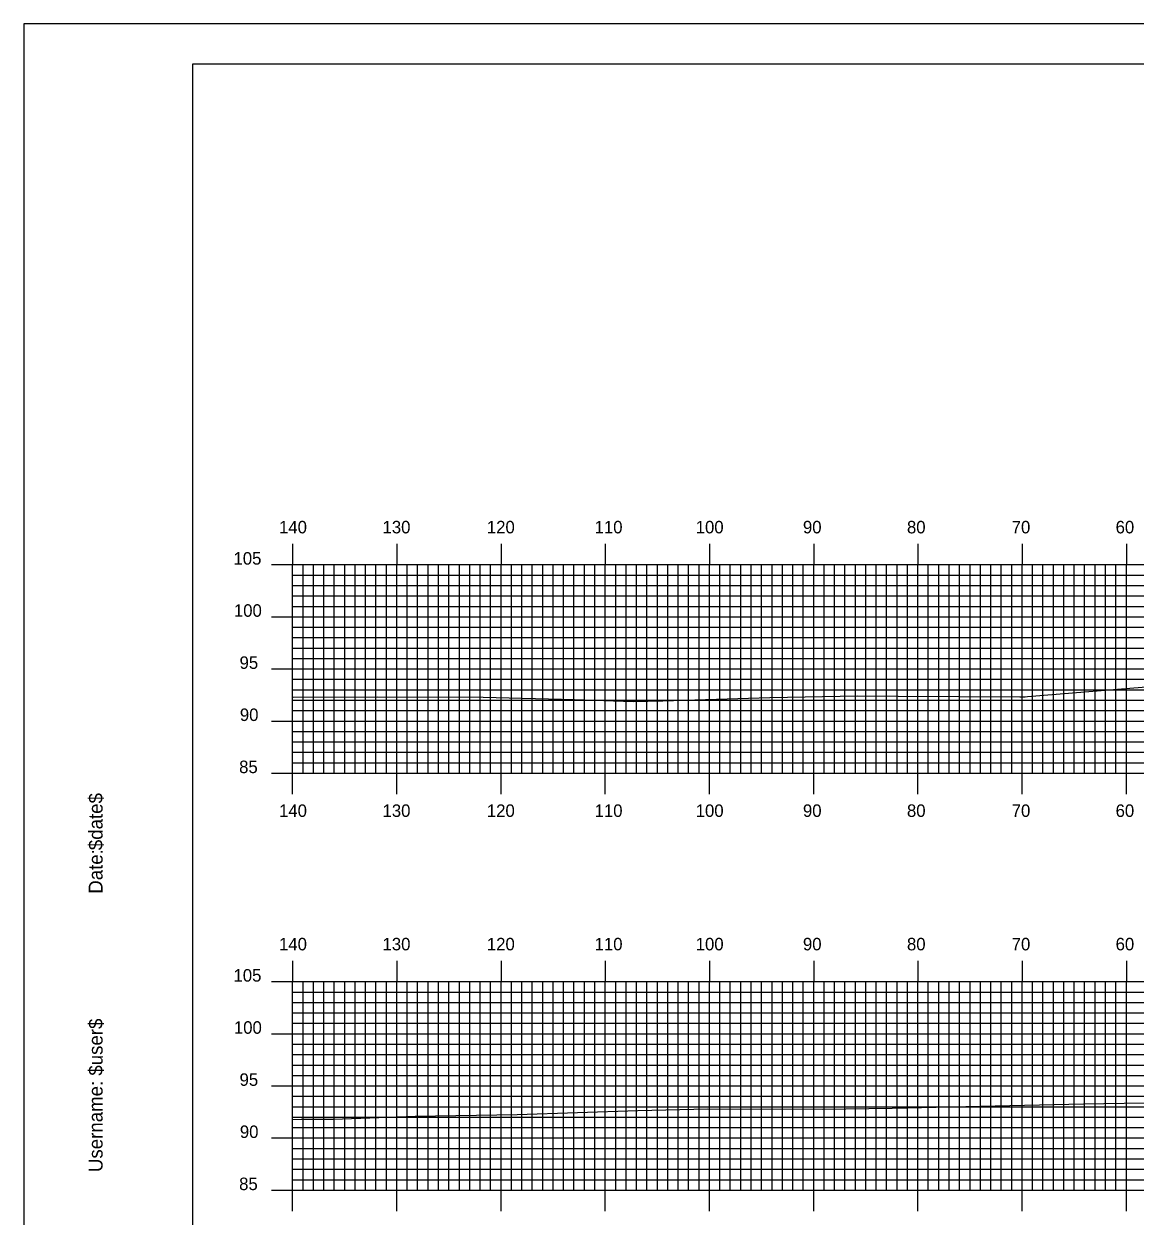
# Model space of a CAD drawing. Extents: x 1763759 to 1764102, y 442591 to 442811.
# Drawn here: x 1763758.5 to 1763865.2, y 442696.2 to 442810.5 of the extents above; entities that cross this region are included whole.
import ezdxf

# ---------------------------------------------------------------- set-up
doc = ezdxf.new("R2010")
doc.units = 0
for name, color, linetype in [('BORDER', 7, 'Continuous'), ('H_V ANNOTATION', 7, 'Continuous'), ('MAJOR', 7, 'Continuous'), ('MINOR', 7, 'Continuous'), ('PLOT BOUNDARY', 7, 'Continuous'), ('S_Roadway_Centerline', 7, 'Continuous')]:
    doc.layers.add(name, color=color, linetype=linetype)

msp = doc.modelspace()

# ---------------------------------------------------------------- linework, layer by layer
at = {"layer": 'BORDER'}
msp.add_lwpolyline([(1763774.72, 442596.67), (1764094.72, 442596.67), (1764094.72, 442806.67), (1763774.72, 442806.67)], close=True, dxfattribs=at)
at = {"layer": 'MAJOR'}
for p, q in [((1763784.32, 442760.67), (1763784.32, 442758.67)), ((1763794.32, 442760.67), (1763794.32, 442758.67)), ((1763804.32, 442760.67), (1763804.32, 442758.67)), ((1763814.32, 442760.67), (1763814.32, 442758.67)), ((1763824.32, 442760.67), (1763824.32, 442758.67)), ((1763834.32, 442760.67), (1763834.32, 442758.67)), ((1763844.32, 442760.67), (1763844.32, 442758.67)), ((1763854.32, 442760.67), (1763854.32, 442758.67)), ((1763864.32, 442760.67), (1763864.32, 442758.67)), ((1763782.31, 442758.67), (1763784.32, 442758.67)), ((1763784.32, 442758.67), (1764064.32, 442758.67)), ((1763784.32, 442738.67), (1763784.32, 442758.67)), ((1763784.32, 442738.67), (1763784.32, 442758.67)), ((1763784.32, 442758.67), (1764064.32, 442758.67)), ((1763794.32, 442738.67), (1763794.32, 442758.67)), ((1763804.32, 442738.67), (1763804.32, 442758.67)), ((1763814.32, 442738.67), (1763814.32, 442758.67)), ((1763824.32, 442738.67), (1763824.32, 442758.67)), ((1763834.32, 442738.67), (1763834.32, 442758.67)), ((1763844.32, 442738.67), (1763844.32, 442758.67)), ((1763854.32, 442738.67), (1763854.32, 442758.67)), ((1763864.32, 442738.67), (1763864.32, 442758.67)), ((1763782.31, 442753.67), (1763784.32, 442753.67)), ((1763784.32, 442753.67), (1764064.32, 442753.67)), ((1763782.31, 442748.67), (1763784.32, 442748.67)), ((1763784.32, 442748.67), (1764064.32, 442748.67)), ((1763782.31, 442743.67), (1763784.32, 442743.67)), ((1763784.32, 442743.67), (1764064.32, 442743.67)), ((1763782.31, 442738.67), (1763784.32, 442738.67)), ((1763784.32, 442738.67), (1764064.32, 442738.67)), ((1763784.32, 442738.67), (1764064.32, 442738.67)), ((1763784.32, 442736.66), (1763784.32, 442738.67)), ((1763794.32, 442736.66), (1763794.32, 442738.67)), ((1763804.32, 442736.66), (1763804.32, 442738.67)), ((1763814.32, 442736.66), (1763814.32, 442738.67)), ((1763824.32, 442736.66), (1763824.32, 442738.67)), ((1763834.32, 442736.66), (1763834.32, 442738.67)), ((1763844.32, 442736.66), (1763844.32, 442738.67)), ((1763854.32, 442736.66), (1763854.32, 442738.67)), ((1763864.32, 442736.66), (1763864.32, 442738.67)), ((1763784.32, 442720.67), (1763784.32, 442718.67)), ((1763794.32, 442720.67), (1763794.32, 442718.67)), ((1763804.32, 442720.67), (1763804.32, 442718.67)), ((1763814.32, 442720.67), (1763814.32, 442718.67)), ((1763824.32, 442720.67), (1763824.32, 442718.67)), ((1763834.32, 442720.67), (1763834.32, 442718.67)), ((1763844.32, 442720.67), (1763844.32, 442718.67)), ((1763854.32, 442720.67), (1763854.32, 442718.67)), ((1763864.32, 442720.67), (1763864.32, 442718.67)), ((1763782.31, 442718.67), (1763784.32, 442718.67)), ((1763784.32, 442718.67), (1764064.32, 442718.67)), ((1763784.32, 442698.67), (1763784.32, 442718.67)), ((1763784.32, 442698.67), (1763784.32, 442718.67)), ((1763784.32, 442718.67), (1764064.32, 442718.67)), ((1763794.32, 442698.67), (1763794.32, 442718.67)), ((1763804.32, 442698.67), (1763804.32, 442718.67)), ((1763814.32, 442698.67), (1763814.32, 442718.67)), ((1763824.32, 442698.67), (1763824.32, 442718.67)), ((1763834.32, 442698.67), (1763834.32, 442718.67)), ((1763844.32, 442698.67), (1763844.32, 442718.67)), ((1763854.32, 442698.67), (1763854.32, 442718.67)), ((1763864.32, 442698.67), (1763864.32, 442718.67)), ((1763782.31, 442713.67), (1763784.32, 442713.67)), ((1763784.32, 442713.67), (1764064.32, 442713.67)), ((1763782.31, 442708.67), (1763784.32, 442708.67)), ((1763784.32, 442708.67), (1764064.32, 442708.67)), ((1763782.31, 442703.67), (1763784.32, 442703.67)), ((1763784.32, 442703.67), (1764064.32, 442703.67)), ((1763782.31, 442698.67), (1763784.32, 442698.67)), ((1763784.32, 442698.67), (1764064.32, 442698.67)), ((1763784.32, 442698.67), (1764064.32, 442698.67)), ((1763784.32, 442696.66), (1763784.32, 442698.67)), ((1763794.32, 442696.66), (1763794.32, 442698.67)), ((1763804.32, 442696.66), (1763804.32, 442698.67)), ((1763814.32, 442696.66), (1763814.32, 442698.67)), ((1763824.32, 442696.66), (1763824.32, 442698.67)), ((1763834.32, 442696.66), (1763834.32, 442698.67)), ((1763844.32, 442696.66), (1763844.32, 442698.67)), ((1763854.32, 442696.66), (1763854.32, 442698.67)), ((1763864.32, 442696.66), (1763864.32, 442698.67))]:
    msp.add_line(p, q, dxfattribs=at)
at = {"layer": 'MINOR'}
for p, q in [((1763785.32, 442738.67), (1763785.32, 442758.67)), ((1763786.32, 442738.67), (1763786.32, 442758.67)), ((1763787.32, 442738.67), (1763787.32, 442758.67)), ((1763788.32, 442738.67), (1763788.32, 442758.67)), ((1763789.32, 442738.67), (1763789.32, 442758.67)), ((1763790.32, 442738.67), (1763790.32, 442758.67)), ((1763791.32, 442738.67), (1763791.32, 442758.67)), ((1763792.32, 442738.67), (1763792.32, 442758.67)), ((1763793.32, 442738.67), (1763793.32, 442758.67)), ((1763795.32, 442738.67), (1763795.32, 442758.67)), ((1763796.32, 442738.67), (1763796.32, 442758.67)), ((1763797.32, 442738.67), (1763797.32, 442758.67)), ((1763798.32, 442738.67), (1763798.32, 442758.67)), ((1763799.32, 442738.67), (1763799.32, 442758.67)), ((1763800.32, 442738.67), (1763800.32, 442758.67)), ((1763801.32, 442738.67), (1763801.32, 442758.67)), ((1763802.32, 442738.67), (1763802.32, 442758.67)), ((1763803.32, 442738.67), (1763803.32, 442758.67)), ((1763805.32, 442738.67), (1763805.32, 442758.67)), ((1763806.32, 442738.67), (1763806.32, 442758.67)), ((1763807.32, 442738.67), (1763807.32, 442758.67)), ((1763808.32, 442738.67), (1763808.32, 442758.67)), ((1763809.32, 442738.67), (1763809.32, 442758.67)), ((1763810.32, 442738.67), (1763810.32, 442758.67)), ((1763811.32, 442738.67), (1763811.32, 442758.67)), ((1763812.32, 442738.67), (1763812.32, 442758.67)), ((1763813.32, 442738.67), (1763813.32, 442758.67)), ((1763815.32, 442738.67), (1763815.32, 442758.67)), ((1763816.32, 442738.67), (1763816.32, 442758.67)), ((1763817.32, 442738.67), (1763817.32, 442758.67)), ((1763818.32, 442738.67), (1763818.32, 442758.67)), ((1763819.32, 442738.67), (1763819.32, 442758.67)), ((1763820.32, 442738.67), (1763820.32, 442758.67)), ((1763821.32, 442738.67), (1763821.32, 442758.67)), ((1763822.32, 442738.67), (1763822.32, 442758.67)), ((1763823.32, 442738.67), (1763823.32, 442758.67)), ((1763825.32, 442738.67), (1763825.32, 442758.67)), ((1763826.32, 442738.67), (1763826.32, 442758.67)), ((1763827.32, 442738.67), (1763827.32, 442758.67)), ((1763828.32, 442738.67), (1763828.32, 442758.67)), ((1763829.32, 442738.67), (1763829.32, 442758.67)), ((1763830.32, 442738.67), (1763830.32, 442758.67)), ((1763831.32, 442738.67), (1763831.32, 442758.67)), ((1763832.32, 442738.67), (1763832.32, 442758.67)), ((1763833.32, 442738.67), (1763833.32, 442758.67)), ((1763835.32, 442738.67), (1763835.32, 442758.67)), ((1763836.32, 442738.67), (1763836.32, 442758.67)), ((1763837.32, 442738.67), (1763837.32, 442758.67)), ((1763838.32, 442738.67), (1763838.32, 442758.67)), ((1763839.32, 442738.67), (1763839.32, 442758.67)), ((1763840.32, 442738.67), (1763840.32, 442758.67)), ((1763841.32, 442738.67), (1763841.32, 442758.67)), ((1763842.32, 442738.67), (1763842.32, 442758.67)), ((1763843.32, 442738.67), (1763843.32, 442758.67)), ((1763845.32, 442738.67), (1763845.32, 442758.67)), ((1763846.32, 442738.67), (1763846.32, 442758.67)), ((1763847.32, 442738.67), (1763847.32, 442758.67)), ((1763848.32, 442738.67), (1763848.32, 442758.67)), ((1763849.32, 442738.67), (1763849.32, 442758.67)), ((1763850.32, 442738.67), (1763850.32, 442758.67)), ((1763851.32, 442738.67), (1763851.32, 442758.67)), ((1763852.32, 442738.67), (1763852.32, 442758.67)), ((1763853.32, 442738.67), (1763853.32, 442758.67)), ((1763855.32, 442738.67), (1763855.32, 442758.67)), ((1763856.32, 442738.67), (1763856.32, 442758.67)), ((1763857.32, 442738.67), (1763857.32, 442758.67)), ((1763858.32, 442738.67), (1763858.32, 442758.67)), ((1763859.32, 442738.67), (1763859.32, 442758.67)), ((1763860.32, 442738.67), (1763860.32, 442758.67)), ((1763861.32, 442738.67), (1763861.32, 442758.67)), ((1763862.32, 442738.67), (1763862.32, 442758.67)), ((1763863.32, 442738.67), (1763863.32, 442758.67)), ((1763784.32, 442757.67), (1764064.32, 442757.67)), ((1763784.32, 442757.67), (1763786.32, 442757.67)), ((1763784.32, 442756.67), (1764064.32, 442756.67)), ((1763784.32, 442756.67), (1763786.32, 442756.67)), ((1763784.32, 442755.67), (1764064.32, 442755.67)), ((1763784.32, 442755.67), (1763786.32, 442755.67)), ((1763784.32, 442754.67), (1764064.32, 442754.67)), ((1763784.32, 442754.67), (1763786.32, 442754.67)), ((1763784.32, 442752.67), (1764064.32, 442752.67)), ((1763784.32, 442752.67), (1763786.32, 442752.67)), ((1763784.32, 442751.67), (1764064.32, 442751.67)), ((1763784.32, 442751.67), (1763786.32, 442751.67)), ((1763784.32, 442750.67), (1764064.32, 442750.67)), ((1763784.32, 442750.67), (1763786.32, 442750.67)), ((1763784.32, 442749.67), (1764064.32, 442749.67)), ((1763784.32, 442749.67), (1763786.32, 442749.67)), ((1763784.32, 442747.67), (1764064.32, 442747.67)), ((1763784.32, 442747.67), (1763786.32, 442747.67)), ((1763784.32, 442746.67), (1764064.32, 442746.67)), ((1763784.32, 442746.67), (1763786.32, 442746.67)), ((1763784.32, 442745.67), (1764064.32, 442745.67)), ((1763784.32, 442745.67), (1763786.32, 442745.67)), ((1763784.32, 442744.67), (1764064.32, 442744.67)), ((1763784.32, 442744.67), (1763786.32, 442744.67)), ((1763784.32, 442742.67), (1764064.32, 442742.67)), ((1763784.32, 442742.67), (1763786.32, 442742.67)), ((1763784.32, 442741.67), (1764064.32, 442741.67)), ((1763784.32, 442741.67), (1763786.32, 442741.67)), ((1763784.32, 442740.67), (1764064.32, 442740.67)), ((1763784.32, 442740.67), (1763786.32, 442740.67)), ((1763784.32, 442739.67), (1764064.32, 442739.67)), ((1763784.32, 442739.67), (1763786.32, 442739.67)), ((1763785.32, 442698.67), (1763785.32, 442718.67)), ((1763786.32, 442698.67), (1763786.32, 442718.67)), ((1763787.32, 442698.67), (1763787.32, 442718.67)), ((1763788.32, 442698.67), (1763788.32, 442718.67)), ((1763789.32, 442698.67), (1763789.32, 442718.67)), ((1763790.32, 442698.67), (1763790.32, 442718.67)), ((1763791.32, 442698.67), (1763791.32, 442718.67)), ((1763792.32, 442698.67), (1763792.32, 442718.67)), ((1763793.32, 442698.67), (1763793.32, 442718.67)), ((1763795.32, 442698.67), (1763795.32, 442718.67)), ((1763796.32, 442698.67), (1763796.32, 442718.67)), ((1763797.32, 442698.67), (1763797.32, 442718.67)), ((1763798.32, 442698.67), (1763798.32, 442718.67)), ((1763799.32, 442698.67), (1763799.32, 442718.67)), ((1763800.32, 442698.67), (1763800.32, 442718.67)), ((1763801.32, 442698.67), (1763801.32, 442718.67)), ((1763802.32, 442698.67), (1763802.32, 442718.67)), ((1763803.32, 442698.67), (1763803.32, 442718.67)), ((1763805.32, 442698.67), (1763805.32, 442718.67)), ((1763806.32, 442698.67), (1763806.32, 442718.67)), ((1763807.32, 442698.67), (1763807.32, 442718.67)), ((1763808.32, 442698.67), (1763808.32, 442718.67)), ((1763809.32, 442698.67), (1763809.32, 442718.67)), ((1763810.32, 442698.67), (1763810.32, 442718.67)), ((1763811.32, 442698.67), (1763811.32, 442718.67)), ((1763812.32, 442698.67), (1763812.32, 442718.67)), ((1763813.32, 442698.67), (1763813.32, 442718.67)), ((1763815.32, 442698.67), (1763815.32, 442718.67)), ((1763816.32, 442698.67), (1763816.32, 442718.67)), ((1763817.32, 442698.67), (1763817.32, 442718.67)), ((1763818.32, 442698.67), (1763818.32, 442718.67)), ((1763819.32, 442698.67), (1763819.32, 442718.67)), ((1763820.32, 442698.67), (1763820.32, 442718.67)), ((1763821.32, 442698.67), (1763821.32, 442718.67)), ((1763822.32, 442698.67), (1763822.32, 442718.67)), ((1763823.32, 442698.67), (1763823.32, 442718.67)), ((1763825.32, 442698.67), (1763825.32, 442718.67)), ((1763826.32, 442698.67), (1763826.32, 442718.67)), ((1763827.32, 442698.67), (1763827.32, 442718.67)), ((1763828.32, 442698.67), (1763828.32, 442718.67)), ((1763829.32, 442698.67), (1763829.32, 442718.67)), ((1763830.32, 442698.67), (1763830.32, 442718.67)), ((1763831.32, 442698.67), (1763831.32, 442718.67)), ((1763832.32, 442698.67), (1763832.32, 442718.67)), ((1763833.32, 442698.67), (1763833.32, 442718.67)), ((1763835.32, 442698.67), (1763835.32, 442718.67)), ((1763836.32, 442698.67), (1763836.32, 442718.67)), ((1763837.32, 442698.67), (1763837.32, 442718.67)), ((1763838.32, 442698.67), (1763838.32, 442718.67)), ((1763839.32, 442698.67), (1763839.32, 442718.67)), ((1763840.32, 442698.67), (1763840.32, 442718.67)), ((1763841.32, 442698.67), (1763841.32, 442718.67)), ((1763842.32, 442698.67), (1763842.32, 442718.67)), ((1763843.32, 442698.67), (1763843.32, 442718.67)), ((1763845.32, 442698.67), (1763845.32, 442718.67)), ((1763846.32, 442698.67), (1763846.32, 442718.67)), ((1763847.32, 442698.67), (1763847.32, 442718.67)), ((1763848.32, 442698.67), (1763848.32, 442718.67)), ((1763849.32, 442698.67), (1763849.32, 442718.67)), ((1763850.32, 442698.67), (1763850.32, 442718.67)), ((1763851.32, 442698.67), (1763851.32, 442718.67)), ((1763852.32, 442698.67), (1763852.32, 442718.67)), ((1763853.32, 442698.67), (1763853.32, 442718.67)), ((1763855.32, 442698.67), (1763855.32, 442718.67)), ((1763856.32, 442698.67), (1763856.32, 442718.67)), ((1763857.32, 442698.67), (1763857.32, 442718.67)), ((1763858.32, 442698.67), (1763858.32, 442718.67)), ((1763859.32, 442698.67), (1763859.32, 442718.67)), ((1763860.32, 442698.67), (1763860.32, 442718.67)), ((1763861.32, 442698.67), (1763861.32, 442718.67)), ((1763862.32, 442698.67), (1763862.32, 442718.67)), ((1763863.32, 442698.67), (1763863.32, 442718.67)), ((1763784.32, 442717.67), (1764064.32, 442717.67)), ((1763784.32, 442717.67), (1763786.32, 442717.67)), ((1763784.32, 442716.67), (1764064.32, 442716.67)), ((1763784.32, 442716.67), (1763786.32, 442716.67)), ((1763784.32, 442715.67), (1764064.32, 442715.67)), ((1763784.32, 442715.67), (1763786.32, 442715.67)), ((1763784.32, 442714.67), (1764064.32, 442714.67)), ((1763784.32, 442714.67), (1763786.32, 442714.67)), ((1763784.32, 442712.67), (1764064.32, 442712.67)), ((1763784.32, 442712.67), (1763786.32, 442712.67)), ((1763784.32, 442711.67), (1764064.32, 442711.67)), ((1763784.32, 442711.67), (1763786.32, 442711.67)), ((1763784.32, 442710.67), (1764064.32, 442710.67)), ((1763784.32, 442710.67), (1763786.32, 442710.67)), ((1763784.32, 442709.67), (1764064.32, 442709.67)), ((1763784.32, 442709.67), (1763786.32, 442709.67)), ((1763784.32, 442707.67), (1764064.32, 442707.67)), ((1763784.32, 442707.67), (1763786.32, 442707.67)), ((1763784.32, 442706.67), (1764064.32, 442706.67)), ((1763784.32, 442706.67), (1763786.32, 442706.67)), ((1763784.32, 442705.67), (1764064.32, 442705.67)), ((1763784.32, 442705.67), (1763786.32, 442705.67)), ((1763784.32, 442704.67), (1764064.32, 442704.67)), ((1763784.32, 442704.67), (1763786.32, 442704.67)), ((1763784.32, 442702.67), (1764064.32, 442702.67)), ((1763784.32, 442702.67), (1763786.32, 442702.67)), ((1763784.32, 442701.67), (1764064.32, 442701.67)), ((1763784.32, 442701.67), (1763786.32, 442701.67)), ((1763784.32, 442700.67), (1764064.32, 442700.67)), ((1763784.32, 442700.67), (1763786.32, 442700.67)), ((1763784.32, 442699.67), (1764064.32, 442699.67)), ((1763784.32, 442699.67), (1763786.32, 442699.67))]:
    msp.add_line(p, q, dxfattribs=at)
at = {"layer": 'PLOT BOUNDARY'}
msp.add_lwpolyline([(1763758.53, 442590.55), (1764098.53, 442590.55), (1764098.53, 442810.55), (1763758.53, 442810.55)], close=True, dxfattribs=at)
at = {"layer": 'S_Roadway_Centerline'}
for points in [[(1763784.32, 442745.96), (1763784.37, 442745.96), (1763792.44, 442745.99), (1763802.6, 442745.95), (1763811.38, 442745.72), (1763817, 442745.55), (1763819.84, 442745.61), (1763830.12, 442745.93), (1763838.54, 442746.08), (1763842.44, 442746.05), (1763854.1, 442746), (1763854.62, 442745.99), (1763854.83, 442746.01), (1763867.39, 442747.03)], [(1763784.32, 442705.45), (1763785.13, 442705.46), (1763788.26, 442705.47), (1763796.09, 442705.77), (1763805.87, 442705.91), (1763817.46, 442706.31), (1763824.15, 442706.48), (1763835.18, 442706.43), (1763841.86, 442706.53), (1763860.2, 442706.95), (1763860.21, 442706.95), (1763860.21, 442706.95), (1763860.21, 442706.95), (1763877.73, 442707.25)]]:
    msp.add_lwpolyline(points, dxfattribs=at)

# ---------------------------------------------------------------- texts
at = {"layer": 'BORDER'}
for s, p in [('$date$', (1763766.09, 442731.28)), ('Date:', (1763766.09, 442727.1)), ('$user$', (1763766.09, 442709.65)), ('Username:', (1763766.09, 442700.4))]:
    msp.add_text(s, height=1.339, rotation=90, dxfattribs=at).set_placement(p)
at = {"layer": 'H_V ANNOTATION'}
for s, p in [('140', (1763783.02, 442761.67)), ('130', (1763792.95, 442761.67)), ('120', (1763802.96, 442761.67)), ('110', (1763813.3, 442761.67)), ('100', (1763823, 442761.67)), ('90', (1763833.29, 442761.67)), ('80', (1763843.27, 442761.67)), ('70', (1763853.32, 442761.67)), ('60', (1763863.29, 442761.67)), ('105', (1763778.65, 442758.67)), ('100', (1763778.69, 442753.67)), ('95', (1763779.23, 442748.67)), ('90', (1763779.26, 442743.67)), ('85', (1763779.19, 442738.67)), ('140', (1763783.02, 442734.47)), ('130', (1763792.95, 442734.47)), ('120', (1763802.96, 442734.47)), ('110', (1763813.3, 442734.47)), ('100', (1763823, 442734.47)), ('90', (1763833.29, 442734.47)), ('80', (1763843.27, 442734.47)), ('70', (1763853.32, 442734.47)), ('60', (1763863.29, 442734.47)), ('140', (1763783.02, 442721.67)), ('130', (1763792.95, 442721.67)), ('120', (1763802.96, 442721.67)), ('110', (1763813.3, 442721.67)), ('100', (1763823, 442721.67)), ('90', (1763833.29, 442721.67)), ('80', (1763843.27, 442721.67)), ('70', (1763853.32, 442721.67)), ('60', (1763863.29, 442721.67)), ('105', (1763778.65, 442718.67)), ('100', (1763778.69, 442713.67)), ('95', (1763779.23, 442708.67)), ('90', (1763779.26, 442703.67)), ('85', (1763779.19, 442698.67))]:
    msp.add_text(s, height=1.2, dxfattribs=at).set_placement(p)
at = {"layer": 'MAJOR'}
for p in [(1763784.31, 442738.67), (1763784.31, 442698.67)]:
    msp.add_text('-', height=0.012, dxfattribs=at).set_placement(p)

doc.saveas('drawing.dxf')
